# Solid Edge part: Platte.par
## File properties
Dokumentum tartalom típus: 0
Last saved by: bmolnar
Revision: 76
Sűrűség: 0,000 kg/m^3
Pontosság: 0,990
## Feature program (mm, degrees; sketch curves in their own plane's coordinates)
base feature "unnamed BaseFeature 1"
thread "unnamed Thread 1"
thread "unnamed Thread 2"
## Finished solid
Body 1: solid body, 65 faces, 114 edges, 88 vertices.
  Faces by surface: plane 38, cylinder 12, cone 10, torus 5
  Edges by curve: line 60, circle 36, spline 18
Bounding box of the edges (mm; curved faces can reach further): 45.147 x 47.553 x 10.000, from (-22.5736, -23.7765, 90.5) to (22.5736, 23.7765, 100.5).
Cylindrical faces by radius (mm): R1.5 x2, R1.75 x2, R2.067 x2, R2.75 x2, R3.25 x2, R5 x1, R8.5 x1
Conical faces (half-angle, radius in mm at the cone's reference point): 45 deg R1.85 x2, 45 deg R2.317 x4, 45 deg R8.75 x1, 60 deg R0.7217 x2, 60 deg R1.1547 x1
Toroidal faces (ring radius, tube radius in mm): R1.6 r0.1 x2, R2.45 r0.3 x2, R4.4 r0.6 x1
Planar faces by outward normal: +y 1, +z 7, -y 1, -z 5, oblique 24
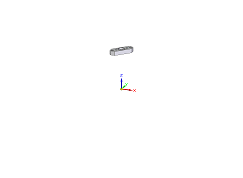
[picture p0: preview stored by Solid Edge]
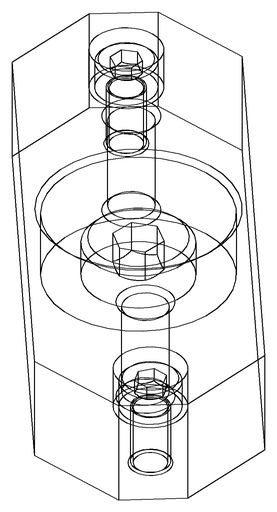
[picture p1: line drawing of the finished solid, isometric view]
